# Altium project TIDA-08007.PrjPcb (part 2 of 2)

## Sheet TIDA-08007_TPS99000Interface.SchDoc: TPS99000 Interface
size 431 x 279 mm; Date: Not shown in title block; ApprovedBy: Not shown in title block; CheckedBy: Not shown in title block; Author: Not shown in title block; CompanyName: Not shown in title block; DrawnBy: Jake Pulliam; Engineer: Not shown in title block; Organization: Not shown in title block; Address1: Not shown in title block; Address2: Not shown in title block; Address3: Not shown in title block; Address4: Not shown in title block; DocumentNumber: 8; Revision: Use project parameter SCH_Rev; SheetNumber: 8; SheetTotal: 10; PageSetup: Record=PageOptions¦CenterHorizontal=True¦CenterVertical=True¦PrintScale=1.00¦XCorrection=1.00¦YCorrection=1.00¦PrintKind=0¦BorderSize=5000000¦LeftOffset=0¦BottomOffset=0¦Orientation=2¦PaperLength=1000¦PaperWidth=1000¦Scale=100¦PaperSource=15¦PrintQuality=600¦MediaType=1¦DitherType=10¦PaperKind=Letter¦PrintScaleMode=1
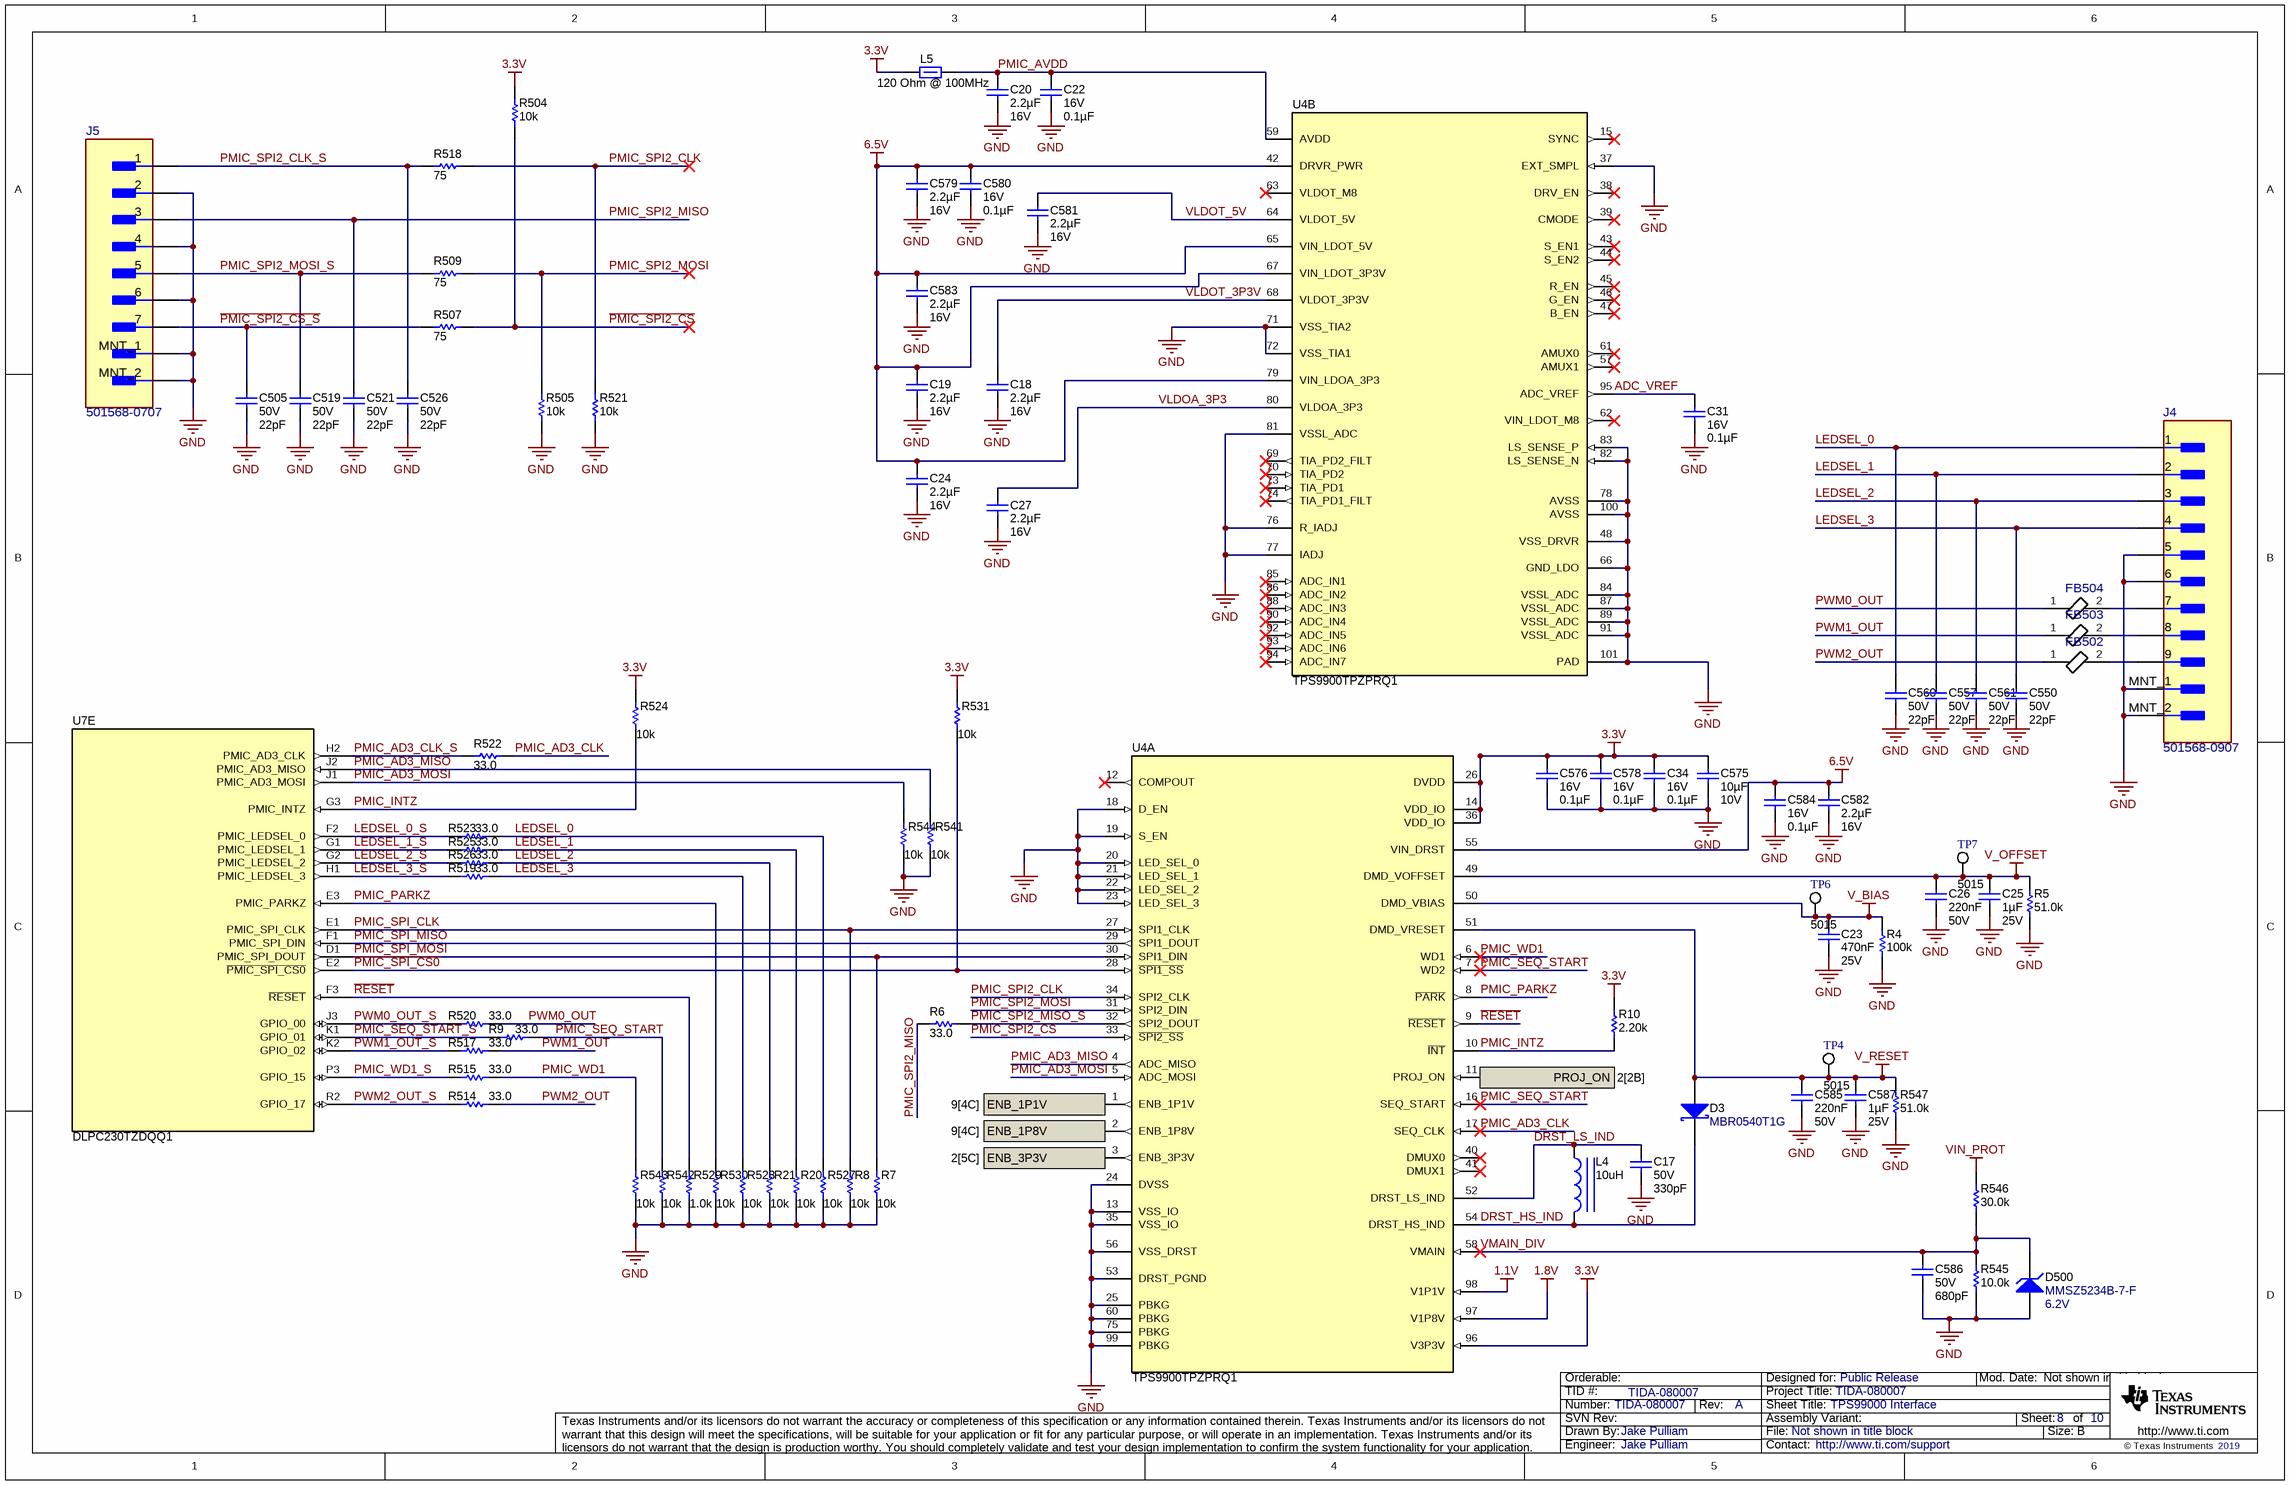
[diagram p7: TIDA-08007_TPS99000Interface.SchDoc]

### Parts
C17  VDC_V: 50V  ValueDisplayed: 330pF  [0402]  (hidden comment: GRM155R71H331KA01D)
C18  Cap_F: 2.2µF  VDC_V: 16V  [0603]  (hidden comment: EMK107BB7225MA-T)
C19  Cap_F: 2.2µF  VDC_V: 16V  [0603]  (hidden comment: EMK107BB7225MA-T)
C20  Cap_F: 2.2µF  VDC_V: 16V  [0603]  (hidden comment: EMK107BB7225MA-T)
C22  VDC_V: 16V  ValueDisplayed: 0.1µF  [0402]  (hidden comment: GCM155R71C104JA55D)
C23  Cap_F: 470nF  VDC_V: 25V  [0603]  (hidden comment: GRM188R71E474KA12D)
C24  Cap_F: 2.2µF  VDC_V: 16V  [0603]  (hidden comment: EMK107BB7225MA-T)
C25  Cap_F: 1µF  VDC_V: 25V  [0603]  (hidden comment: GCM188R71E105KA64D)
C26  Cap_F: 220nF  VDC_V: 50V  [0603]  (hidden comment: GCM188R71H224KA64D)
C27  Cap_F: 2.2µF  VDC_V: 16V  [0603]  (hidden comment: EMK107BB7225MA-T)
C31  VDC_V: 16V  ValueDisplayed: 0.1µF  [0402]  (hidden comment: GCM155R71C104JA55D)
C34  VDC_V: 16V  ValueDisplayed: 0.1µF  [0402]  (hidden comment: GCM155R71C104JA55D)
C505  VDC_V: 50V  ValueDisplayed: 22pF  [0402]  (hidden comment: CGA2B2NP01H220J050BA)
C519  VDC_V: 50V  ValueDisplayed: 22pF  [0402]  (hidden comment: CGA2B2NP01H220J050BA)
C521  VDC_V: 50V  ValueDisplayed: 22pF  [0402]  (hidden comment: CGA2B2NP01H220J050BA)
C526  VDC_V: 50V  ValueDisplayed: 22pF  [0402]  (hidden comment: CGA2B2NP01H220J050BA)
C550  VDC_V: 50V  ValueDisplayed: 22pF  [0402]  (hidden comment: CGA2B2NP01H220J050BA)
C557  VDC_V: 50V  ValueDisplayed: 22pF  [0402]  (hidden comment: CGA2B2NP01H220J050BA)
C560  VDC_V: 50V  ValueDisplayed: 22pF  [0402]  (hidden comment: CGA2B2NP01H220J050BA)
C561  VDC_V: 50V  ValueDisplayed: 22pF  [0402]  (hidden comment: CGA2B2NP01H220J050BA)
C575  Cap_F: 10µF  VDC_V: 10V  [0805_HV]  (hidden comment: C2012X7R1A106M125AC)
C576  VDC_V: 16V  ValueDisplayed: 0.1µF  [0402]  (hidden comment: GCM155R71C104JA55D)
C578  VDC_V: 16V  ValueDisplayed: 0.1µF  [0402]  (hidden comment: GCM155R71C104JA55D)
C579  Cap_F: 2.2µF  VDC_V: 16V  [0603]  (hidden comment: EMK107BB7225MA-T)
C580  VDC_V: 16V  ValueDisplayed: 0.1µF  [0402]  (hidden comment: GCM155R71C104JA55D)
C581  Cap_F: 2.2µF  VDC_V: 16V  [0603]  (hidden comment: EMK107BB7225MA-T)
C582  Cap_F: 2.2µF  VDC_V: 16V  [0603]  (hidden comment: EMK107BB7225MA-T)
C583  Cap_F: 2.2µF  VDC_V: 16V  [0603]  (hidden comment: EMK107BB7225MA-T)
C584  VDC_V: 16V  ValueDisplayed: 0.1µF  [0402]  (hidden comment: GCM155R71C104JA55D)
C585  Cap_F: 220nF  VDC_V: 50V  [0603]  (hidden comment: GCM188R71H224KA64D)
C586  VDC_V: 50V  ValueDisplayed: 680pF  [0402]  (hidden comment: CGA2B2X7R1H681K050BA)
C587  Cap_F: 1µF  VDC_V: 25V  [0603]  (hidden comment: GCM188R71E105KA64D)
D3  MBR0540T1G  [SOD-123]
D500  MMSZ5234B-7-F  value 6.2V  [SOD-123]
FB502  FBMH1608HM101-TV  [FP-FBMH1608HM101-TV_0603-MFG]  (value not drawn)
FB503  FBMH1608HM101-TV  [FP-FBMH1608HM101-TV_0603-MFG]  (value not drawn)
FB504  FBMH1608HM101-TV  [FP-FBMH1608HM101-TV_0603-MFG]  (value not drawn)
J4  501568-0907  [FP-501568-0907_HDR9-MFG]
J5  501568-0707  [FP-501568-0707_HDR7-MFG]
L4  ValueDisplayed: 10uH  [FDSD0420]  (hidden comment: FDSD0420D-100M)
L5  120 Ohm @ 100MHz  [0402]
R4  ValueDisplayed: 100k  [0402]  (hidden comment: ERJ-2RKF1003X)
R5  ValueDisplayed: 51.0k  [0402]  (hidden comment: ERJ-2RKF5102X)
R6  ValueDisplayed: 33.0  [0402]  (hidden comment: ERJ-2RKF33R0X)
R7  ValueDisplayed: 10k  [0402]  (hidden comment: ERJ-2GEJ103X)
R8  ValueDisplayed: 10k  [0402]  (hidden comment: ERJ-2GEJ103X)
R9  ValueDisplayed: 33.0  [0402]  (hidden comment: ERJ-2RKF33R0X)
R10  ValueDisplayed: 2.20k  [0402]  (hidden comment: ERJ-2RKF2201X)
R20  ValueDisplayed: 10k  [0402]  (hidden comment: ERJ-2GEJ103X)
R21  ValueDisplayed: 10k  [0402]  (hidden comment: ERJ-2GEJ103X)
R504  ValueDisplayed: 10k  [0402]  (hidden comment: ERJ-2GEJ103X)
R505  ValueDisplayed: 10k  [0402]  (hidden comment: ERJ-2GEJ103X)
R507  ValueDisplayed: 75  [0805_HV]  (hidden comment: ERJ-6GEYJ750V)
R509  ValueDisplayed: 75  [0805_HV]  (hidden comment: ERJ-6GEYJ750V)
R514  ValueDisplayed: 33.0  [0402]  (hidden comment: ERJ-2RKF33R0X)
R515  ValueDisplayed: 33.0  [0402]  (hidden comment: ERJ-2RKF33R0X)
R517  ValueDisplayed: 33.0  [0402]  (hidden comment: ERJ-2RKF33R0X)
R518  ValueDisplayed: 75  [0805_HV]  (hidden comment: ERJ-6GEYJ750V)
R519  ValueDisplayed: 33.0  [0402]  (hidden comment: ERJ-2RKF33R0X)
R520  ValueDisplayed: 33.0  [0402]  (hidden comment: ERJ-2RKF33R0X)
R521  ValueDisplayed: 10k  [0402]  (hidden comment: ERJ-2GEJ103X)
R522  ValueDisplayed: 33.0  [0402]  (hidden comment: ERJ-2RKF33R0X)
R523  ValueDisplayed: 33.0  [0402]  (hidden comment: ERJ-2RKF33R0X)
R524  ValueDisplayed: 10k  [0402]  (hidden comment: ERJ-2GEJ103X)
R525  ValueDisplayed: 33.0  [0402]  (hidden comment: ERJ-2RKF33R0X)
R526  ValueDisplayed: 33.0  [0402]  (hidden comment: ERJ-2RKF33R0X)
R527  ValueDisplayed: 10k  [0402]  (hidden comment: ERJ-2GEJ103X)
R528  ValueDisplayed: 10k  [0402]  (hidden comment: ERJ-2GEJ103X)
R529  ValueDisplayed: 1.0k  [0402]  (hidden comment: ERJ-2GEJ102X)
R530  ValueDisplayed: 10k  [0402]  (hidden comment: ERJ-2GEJ103X)
R531  ValueDisplayed: 10k  [0402]  (hidden comment: ERJ-2GEJ103X)
R541  ValueDisplayed: 10k  [0402]  (hidden comment: ERJ-2GEJ103X)
R542  ValueDisplayed: 10k  [0402]  (hidden comment: ERJ-2GEJ103X)
R543  ValueDisplayed: 10k  [0402]  (hidden comment: ERJ-2GEJ103X)
R544  ValueDisplayed: 10k  [0402]  (hidden comment: ERJ-2GEJ103X)
R545  ValueDisplayed: 10.0k  [0603]  (hidden comment: ERJ-3EKF1002V)
R546  ValueDisplayed: 30.0k  [0603]  (hidden comment: ERJ-3EKF3002V)
R547  ValueDisplayed: 51.0k  [0402]  (hidden comment: ERJ-2RKF5102X)
TP4  5015  [Testpoint_Keystone_Miniature]
TP6  5015  [Testpoint_Keystone_Miniature]
TP7  5015  [Testpoint_Keystone_Miniature]
U4  TPS9900TPZPRQ1  [PZP0100K]  (parts A,B of 2)
U7  DLPC230TZDQQ1  [ZDQ0324]  (part E of 9)

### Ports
ENB_1P1V (out, see 9[4C]), ENB_1P8V (out, see 9[4C]), ENB_3P3V (out, see 2[5C]), PROJ_ON (in, see 2[2B])

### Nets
1.1V: U4.98(V1P1V)
1.8V: U4.97(V1P8V)
3.3V: C34.1 C575.1 C576.1 C578.1 L5.1 R10.2 R504.2 R524.2 R531.2 U4.14(VDD_IO) U4.26(DVDD) U4.36(VDD_IO) U4.96(V3P3V)
6.5V: C19.1 C24.1 C579.1 C580.1 C582.1 C583.1 C584.1 U4.42(DRVR_PWR) U4.55(VIN_DRST) U4.65(VIN_LDOT_5V) U4.67(VIN_LDOT_3P3V) U4.79(VIN_LDOA_3P3)
GND: C17.2 C18.2 C19.2 C20.2 C22.2 C23.2 C24.2 C25.2 C26.2 C27.2 C31.2 C34.2 C505.2 C519.2 C521.2 C526.2 C550.2 C557.2 C560.2 C561.2 C575.2 C576.2 C578.2 C579.2 C580.2 C581.2 C582.2 C583.2 C584.2 C585.2 C586.2 C587.2 D500.2(A) J4.5 J4.6 J4.10(MNT_1) J4.11(MNT_2) J5.2 J5.4 J5.6 J5.8(MNT_1) J5.9(MNT_2) R4.1 R5.1 R7.1 R8.1 R20.1 R21.1 R505.1 R521.1 R527.1 R528.1 R529.1 R530.1 R541.1 R542.1 R543.1 R544.1 R545.1 R547.1 U4.13(VSS_IO) U4.18(D_EN) U4.19(S_EN) U4.20(LED_SEL_0) U4.21(LED_SEL_1) U4.22(LED_SEL_2) U4.23(LED_SEL_3) U4.24(DVSS) U4.25(PBKG) U4.35(VSS_IO) U4.37(EXT_SMPL) U4.48(VSS_DRVR) U4.53(DRST_PGND) U4.56(VSS_DRST) U4.60(PBKG) U4.66(GND_LDO) U4.71(VSS_TIA2) U4.72(VSS_TIA1) U4.75(PBKG) U4.76(R_IADJ) U4.77(IADJ) U4.78(AVSS) U4.81(VSSL_ADC) U4.82(LS_SENSE_N) U4.83(LS_SENSE_P) U4.84(VSSL_ADC) U4.87(VSSL_ADC) U4.89(VSSL_ADC) U4.91(VSSL_ADC) U4.99(PBKG) U4.100(AVSS) U4.101(PAD)
V_BIAS: C23.1 R4.2 TP6.1 U4.50(DMD_VBIAS)
V_OFFSET: C25.1 C26.1 R5.2 TP7.1 U4.49(DMD_VOFFSET)
V_RESET: C585.1 C587.1 D3.2(A) R547.2 TP4.1 U4.51(DMD_VRESET)
VIN_PROT: R546.2
~{PMIC_SPI2_CS}: R504.1 R507.2 U4.33(~{SPI2_SS})
~{PMIC_SPI2_CS_S}: C505.1 J5.7 R507.1
~{PMIC_SPI_CS0}: R531.1 U4.28(~{SPI1_SS}) U7.E2(~{PMIC_SPI_CS0})
~{RESET}: R529.2 U4.9(~{RESET}) U7.F3(~{RESET})
ADC_VREF: C31.1 U4.95(ADC_VREF)
DRST_HS_IND: D3.1(K) L4.2 U4.54(DRST_HS_IND)
DRST_LS_IND: C17.1 L4.1 U4.52(DRST_LS_IND)
ENB_1P1V: U4.1(ENB_1P1V) ; port ENB_1P1V
ENB_1P8V: U4.2(ENB_1P8V) ; port ENB_1P8V
ENB_3P3V: U4.3(ENB_3P3V) ; port ENB_3P3V
LEDSEL_0: C560.1 J4.1 R523.2 R527.2
LEDSEL_0_S: R523.1 U7.F2(PMIC_LEDSEL_0)
LEDSEL_1: C557.1 J4.2 R20.2 R525.2
LEDSEL_1_S: R525.1 U7.G1(PMIC_LEDSEL_1)
LEDSEL_2: C561.1 J4.3 R21.2 R526.2
LEDSEL_2_S: R526.1 U7.G2(PMIC_LEDSEL_2)
LEDSEL_3: C550.1 J4.4 R519.2 R528.2
LEDSEL_3_S: R519.1 U7.H1(PMIC_LEDSEL_3)
PMIC_AD3_CLK: R522.2 U4.17(SEQ_CLK)
PMIC_AD3_CLK_S: R522.1 U7.H2(PMIC_AD3_CLK)
PMIC_AD3_MISO: R541.2 U4.4(ADC_MISO) U7.J2(PMIC_AD3_MISO)
PMIC_AD3_MOSI: R544.2 U4.5(ADC_MOSI) U7.J1(PMIC_AD3_MOSI)
PMIC_AVDD: C20.1 C22.1 L5.2 U4.59(AVDD)
PMIC_INTZ: R10.1 R524.1 U4.10(~{INT}) U7.G3(PMIC_INTZ)
PMIC_PARKZ: R530.2 U4.8(~{PARK}) U7.E3(PMIC_PARKZ)
PMIC_SEQ_START: R9.2 R542.2 U4.7(WD2) U4.16(SEQ_START)
PMIC_SEQ_START_S: R9.1 U7.K1(GPIO_01)
PMIC_SPI2_CLK: R518.2 R521.2 U4.34(SPI2_CLK)
PMIC_SPI2_CLK_S: C526.1 J5.1 R518.1
PMIC_SPI2_MISO: C521.1 J5.3 R6.1
PMIC_SPI2_MISO_S: R6.2 U4.32(SPI2_DOUT)
PMIC_SPI2_MOSI: R505.2 R509.2 U4.31(SPI2_DIN)
PMIC_SPI2_MOSI_S: C519.1 J5.5 R509.1
PMIC_SPI_CLK: R8.2 U4.27(SPI1_CLK) U7.E1(PMIC_SPI_CLK)
PMIC_SPI_MISO: U4.29(SPI1_DOUT) U7.F1(PMIC_SPI_DIN)
PMIC_SPI_MOSI: R7.2 U4.30(SPI1_DIN) U7.D1(PMIC_SPI_DOUT)
PMIC_WD1: R515.2 R543.2 U4.6(WD1)
PMIC_WD1_S: R515.1 U7.P3(GPIO_15)
PROJ_ON: U4.11(PROJ_ON) ; port PROJ_ON
PWM0_OUT: FB504.1 R520.2
PWM0_OUT_S: R520.1 U7.J3(GPIO_00)
PWM1_OUT: FB503.1 R517.2
PWM1_OUT_S: R517.1 U7.K2(GPIO_02)
PWM2_OUT: FB502.1 R514.2
PWM2_OUT_S: R514.1 U7.R2(GPIO_17)
VLDOA_3P3: C27.1 U4.80(VLDOA_3P3)
VLDOT_3P3V: C18.1 U4.68(VLDOT_3P3V)
VLDOT_5V: C581.1 U4.64(VLDOT_5V)
VMAIN_DIV: C586.1 D500.1(K) R545.2 R546.1 U4.58(VMAIN)
NetFB502_2: FB502.2 J4.9
NetFB503_2: FB503.2 J4.8
NetFB504_2: FB504.2 J4.7

Not connected (* = marked no-connect by the designer): U4 12(COMPOUT)* 15(SYNC)* 38(DRV_EN)* 39(CMODE)* 40(DMUX0)* 41(DMUX1)* 43(S_EN1)* 44(S_EN2)* 45(R_EN)* 46(G_EN)* 47(B_EN)* 57(AMUX1)* 61(AMUX0)* 62(VIN_LDOT_M8)* 63(VLDOT_M8)* 69(TIA_PD2_FILT)* 70(TIA_PD2)* 73(TIA_PD1)* 74(TIA_PD1_FILT)* 85(ADC_IN1)* 86(ADC_IN2)* 88(ADC_IN3)* 90(ADC_IN4)* 92(ADC_IN5)* 93(ADC_IN6)* 94(ADC_IN7)*

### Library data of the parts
C17 = CMP-0006687-2: CAP, CERM, 330 pF, 50 V, +/- 10%, X7R, 0402; Manufacturer: MuRata; TaMin_C: -55°C; Polarized: N; SizeAreaWB_mm2: 3; Value1: Unknown; U/M: EA; Value: 330pF; TaMax_C: 125°C; SizeZ_mm: 0.6; SizeX_mm: 1; SizeY_mm: 0.5; AEC Category: Q200
C18-C20 C24 C27 C579 C581-C583 = CMP-0064934-4: CAP, CERM, 2.2 uF, 16 V,+/- 10%, X7R, 0603; Manufacturer: Taiyo Yuden; TaMin_C: -55°C; Polarized: N; SizeAreaWB_mm2: 4.68; Value1: Unknown; U/M: EA; Value: 2.2uF; TaMax_C: 125°C; SizeZ_mm: 1; SizeX_mm: 1.6; SizeY_mm: 0.8; SizeArea_mm2: 1.28; AEC Category: Q200
C22 C31 C34 C576 C578 C580 C584 = CMP-0080702-1: CAP, CERM, 0.1 µF, 16 V,+/- 5%, X7R, AEC-Q200 Grade 1, 0402; Manufacturer: MuRata; Cap_F: 100nF; SizeAreaWB_mm2: 3; SizeArea_mm2: 0.5; AEC Qualified: Y; AEC Category: Q200; Value: 0.1uF; TaMax_C: 125°C; SizeZ_mm: 0.6; AEC Grade: 1; Polarized: N; TaMin_C: -55°C; U/M: EA
C23 = CMP-0007424-4: CAP, CERM, 0.47 uF, 25 V, +/- 10%, X7R, 0603; Manufacturer: MuRata; TaMin_C: -55°C; Polarized: N; SizeAreaWB_mm2: 4.68; Value1: Unknown; U/M: EA; Value: 0.47uF; TaMax_C: 125°C; SizeZ_mm: 1; SizeX_mm: 1.6; SizeY_mm: 0.8; SizeArea_mm2: 1.28; AEC Category: Q200
C25 C587 = CMP-0007139-4: CAP, CERM, 1 uF, 25 V, +/- 10%, X7R, AEC-Q200 Grade 1, 0603; Manufacturer: MuRata; TaMin_C: -55°C; Polarized: N; SizeAreaWB_mm2: 4.68; Value1: Unknown; U/M: EA; Value: 1uF; TaMax_C: 125°C; SizeZ_mm: 1; SizeX_mm: 1.6; SizeY_mm: 0.8; SizeArea_mm2: 1.28; AEC Qualified: Y; AEC Category: Q200
C26 C585 = CMP-0007145-4: CAP, CERM, 0.22 uF, 50 V, +/- 10%, X7R, AEC-Q200 Grade 1, 0603; Manufacturer: MuRata; TaMin_C: -55°C; Polarized: N; SizeAreaWB_mm2: 4.68; Value1: Unknown; U/M: EA; Value: 0.22uF; TaMax_C: 125°C; SizeZ_mm: 1; SizeX_mm: 1.6; SizeY_mm: 0.8; SizeArea_mm2: 1.28; AEC Qualified: Y; AEC Category: Q200
C505 C519 C521 C526 C550 C557 C560 C561 = CMP-0006311-2: CAP, CERM, 22 pF, 50 V, +/- 5%, C0G/NP0, AEC-Q200 Grade 1, 0402; Manufacturer: TDK; TaMin_C: -55°C; Polarized: N; SizeAreaWB_mm2: 3; Value1: Unknown; U/M: EA; Value: 22pF; TaMax_C: 125°C; SizeZ_mm: 0.6; SizeX_mm: 1; SizeY_mm: 0.5; AEC Qualified: Y; AEC Category: Q200
C575 = CMP-0007864-2: CAP, CERM, 10 uF, 10 V, +/- 20%, X7R, 0805; Manufacturer: TDK; TaMin_C: -55°C; Polarized: N; SizeAreaWB_mm2: 6.75; Value1: Unknown; U/M: EA; Value: 10uF; TaMax_C: 125°C; SizeZ_mm: 1.45; SizeX_mm: 2; SizeY_mm: 1.25; Cap_Case: 0805; SizeArea_mm2: 2.5; AEC Category: Q200
C586 = CMP-0006322-2: CAP, CERM, 680 pF, 50 V, +/- 10%, X7R, AEC-Q200 Grade 1, 0402; Manufacturer: TDK; TaMin_C: -55°C; ESR_ohm: 3.07785; Polarized: N; SizeAreaWB_mm2: 3; Value1: 3.07785 ohm; U/M: EA; Value: 680pF; TaMax_C: 125°C; SizeZ_mm: 0.6; SizeX_mm: 1; SizeY_mm: 0.5; AEC Qualified: Y; IRMS_A: 257.63mA; AEC Category: Q200
D3 = CMP-0028526-2: Diode, Schottky, 40 V, 0.5 A, SOD-123; Manufacturer: ON Semiconductor; Green_REACh: Passed; SizeY_mm: 1.7; Io_A: 500mA; SizeArea_mm2: 6.545; RJC_CperW: 118; Green_Lifecycle: Active; Vr_V: 40V; Vf_V: 510mV; TJmax_C: 150°C; AEC Category: Q101; SizeAreaWB_mm2: 13.095; Value1: 0.5A; SizeZ_mm: 1.35; SizeX_mm: 3.85; Value2: 0.51V; Value: 40V
D500 = CMP-0005805-3: Diode, Zener, 6.2 V, 500 mW, SOD-123; Manufacturer: Diodes Inc.; SizeY_mm: 1.7; AEC Category: Q101; SizeAreaWB_mm2: 13.095; SizeZ_mm: 1.35; SizeArea_mm2: 6.545; RJA_CperW: 350; Power_W: 500mW; Value1: 0.5W; SizeX_mm: 3.85
FB502-FB504 = CMP-0086561-1: Ind Chip Bead Multi-Layer 100Ohm 25% 100MHz Ferrite 2.5A 0603 T/R; Manufacturer: Taiyo Yuden; Symbol Name: SYM-FBMH1608HM101-TV; SizeZ_mm: 0.9mm; DCR_ohm: 0.035
J4 = CMP-0086592-1: CONN HEADER SMD R/A 9POS 1MM; Manufacturer: Molex; Row_Count: 1; Current_A: 1A; Symbol Name: SYM-501568-0907; ContactFinish: Tin,Nickel; Voltage_V: 50V
J5 = CMP-0087313-1: CONN HEADER 1MM 7POS SMD R/A; Manufacturer: Molex; Voltage_V: 50V; Row_Count: 1; ContactFinish: Tin,Nickel; Current_A: 1A
L4 = CMP-0058981-1: Inductor, Shielded, 10 uH, 1.7 A, 0.2 ohm, AEC-Q200 Grade 1, SMD; Manufacturer: MuRata Toko; Isat: 1.7A @ 30% inductance drop; Irms: 2.5A @ 40C rise; SizeAreaWB_mm2: 27.04; DCR_ohm: 0.2; Value1: 0.2 ohm; Value: 10uH; Imax_A: 1.7A; SizeZ_mm: 2; SizeX_mm: 4.2; SizeArea_mm2: 17.64; Ind_H: 10µH; AEC Qualified: Y; AEC Grade: 1; AEC Category: Q200
L5 = CMP-0075677-1: Ferrite Bead, 120 ohm @ 100 MHz, 0.4 A, 0402; Manufacturer: TDK; PartNumber: MMZ1005Y121CT000; ZTyp@100MHz_Ohm: 120; SizeAreaWB_mm2: 3.0; DCR_ohm: 0.18; Value1: 0.18 ohm; Value: 120 ohm; Imax_A: 400mA; SizeZ_mm: 0.6; SizeX_mm: 1.0; SizeY_mm: 0.5; Value2: 0.4A
R4 = CMP-0026659-1: RES, 100 k, 1%, 0.1 W, 0402; Manufacturer: Panasonic; Power_W: 100mW; TempCo: 100 ppm/C; U/M: EA; Value: 100k; EIA_Code: E96; SizeX_mm: 1; SizeY_mm: 0.5; SizeZ_mm: 0.6; Value2: 0.1W; VDC_V: 50V; AEC Category: Q200
R5 R547 = CMP-0026705-1: RES, 51.0 k, 1%, 0.1 W, AEC-Q200 Grade 0, 0402; Manufacturer: Panasonic; Power_W: 100mW; TempCo: 100 ppm/C; Value_Code: 51k0; U/M: EA; Value: 51.0k; Res_ohm: 51k; SizeX_mm: 1; SizeY_mm: 0.5; SizeZ_mm: 0.6; Value2: 0.1W; AEC Qualified: Y; VDC_V: 50V; AEC Grade: 0; AEC Category: Q200
R6 R9 R514 R515 R517 R519 R520 R522 R523 R525 R526 = CMP-0026696-1: RES, 33.0, 1%, 0.1 W, 0402; Manufacturer: Panasonic; Power_W: 100mW; TempCo: 100 ppm/C; Value_Code: 33R0; U/M: EA; Value: 33.0; Res_ohm: 33; SizeX_mm: 1; SizeY_mm: 0.5; SizeZ_mm: 0.6; Value2: 0.1W; VDC_V: 50V; AEC Category: Q200
R7 R8 R20 R21 R504 R505 R521 R524 R527 R528 R530 R531 R541-R544 = CMP-0026994-4: RES, 10 k, 5%, 0.1 W, AEC-Q200 Grade 0, 0402; Manufacturer: Panasonic; Power_W: 100mW; TempCo: 200 ppm/C; Value_Code: 10k0; U/M: EA; Value: 10k; EIA_Code: E24; SizeX_mm: 1; SizeY_mm: 0.5; SizeZ_mm: 0.6; Value2: 0.1W; AEC Qualified: Y; VDC_V: 50V; AEC Grade: 0; AEC Category: Q200
R10 = CMP-0026681-1: RES, 2.20 k, 1%, 0.1 W, 0402; Manufacturer: Panasonic; Power_W: 100mW; TempCo: 100 ppm/C; Value_Code: 2k20; U/M: EA; Value: 2.20k; Res_ohm: 2.2k; SizeX_mm: 1; SizeY_mm: 0.5; SizeZ_mm: 0.6; Value2: 0.1W; VDC_V: 50V; AEC Category: Q200
R507 R509 R518 = CMP-0020766-3: RES, 75, 5%, 0.125 W, AEC-Q200 Grade 0, 0805; Manufacturer: Panasonic; Power_W: 125mW; TempCo: 200 ppm/C; Value_Code: 75R0; Value: 75; EIA_Code: E24; SizeX_mm: 2; SizeY_mm: 1.25; SizeZ_mm: 1.45; Value2: 0.125W; SizeArea_mm2: 2.5; AEC Qualified: Y; VDC_V: 150V; AEC Category: Q200; AEC Grade: 0; SizeAreaWB_mm2: 6.75
R529 = CMP-0078193-1: RES, 1.0 k, 5%, 0.1 W, AEC-Q200 Grade 0, 0402; Manufacturer: Panasonic; Value_Code: 1k00; SizeArea_mm2: 0.5; AEC Qualified: Y; AEC Category: Q200; Res_ohm: 1k; Value: 1.0k; SizeZ_mm: 0.6; Green_REACh: Passed; EIA_Code: E24; TempCo: 200 ppm/C; AEC Grade: 0; Power_W: 100mW; VDC_V: 50V; Value2: 0.1W; Green_Lifecycle: Active; U/M: EA; SizeX_mm: 1
R545 = CMP-0022684-3: RES, 10.0 k, 1%, 0.1 W, 0603; Manufacturer: Panasonic; Power_W: 100mW; TempCo: 100 ppm/C; Value_Code: 10k0; U/M: EA; Value: 10.0k; EIA_Code: E96; Res_ohm: 10k; SizeX_mm: 1.6; SizeY_mm: 0.8; SizeZ_mm: 1; Value2: 0.1W; SizeArea_mm2: 1.28; VDC_V: 75V; AEC Category: Q200
R546 = CMP-0022695-3: RES, 30.0 k, 1%, 0.1 W, AEC-Q200 Grade 0, 0603; Manufacturer: Panasonic; Power_W: 100mW; TempCo: 100 ppm/C; Value_Code: 30k0; U/M: EA; Value: 30.0k; Res_ohm: 30k; SizeX_mm: 1.6; SizeY_mm: 0.8; SizeZ_mm: 1; Value2: 0.1W; SizeArea_mm2: 1.28; AEC Qualified: Y; VDC_V: 75V; AEC Grade: 0; AEC Category: Q200
TP4 TP6 TP7 = CMP-0055152-1: Test Point, Miniature, SMT; Manufacturer: Keystone; CNHeader: FALSE; Green_Lifecycle: Active; Green_REACh: Passed; CT: TRUE
U4 = CMP-0750180-3: DLP® System Management and Illumination Controller for DLP553x-Q1 Chipset, PZP0100K (TQFP-100); Alternate Manufacturer: Texas Instruments; SizeX_mm: 16; Rating: Automotive; AEC Qualified: Y; SizeZ_mm: 1.2; SizeAreaWB_mm2: 324; AEC Category: Q200; CompType: IC; SizeArea_mm2: 256
U7 = CMP-0750177-3: DLP® Automotive DMD Controller for DLP553x-Q1 Chipset, ZDQ0324 (BGA-324); Manufacturer: Texas Instruments; SizeAreaWB_mm2: 625; SizeArea_mm2: 529; SizeX_mm: 23; AEC Qualified: Y; CompType: IC; AEC Category: Q200; SizeZ_mm: 2.352

## Sheet TIDA-08007_Power.SchDoc: Power
size 431 x 279 mm; Date: Not shown in title block; ApprovedBy: Not shown in title block; CheckedBy: Not shown in title block; Author: Not shown in title block; CompanyName: Not shown in title block; DrawnBy: Jake Pulliam; Engineer: Not shown in title block; Organization: Not shown in title block; Address1: Not shown in title block; Address2: Not shown in title block; Address3: Not shown in title block; Address4: Not shown in title block; DocumentNumber: 9; Revision: Use project parameter SCH_Rev; SheetNumber: 9; SheetTotal: 10; PageSetup: Record=PageOptions¦CenterHorizontal=True¦CenterVertical=True¦PrintScale=1.00¦XCorrection=1.00¦YCorrection=1.00¦PrintKind=0¦BorderSize=5000000¦LeftOffset=0¦BottomOffset=0¦Orientation=2¦PaperLength=1000¦PaperWidth=1000¦Scale=100¦PaperSource=15¦PrintQuality=600¦MediaType=1¦DitherType=10¦PaperKind=Letter¦PrintScaleMode=1
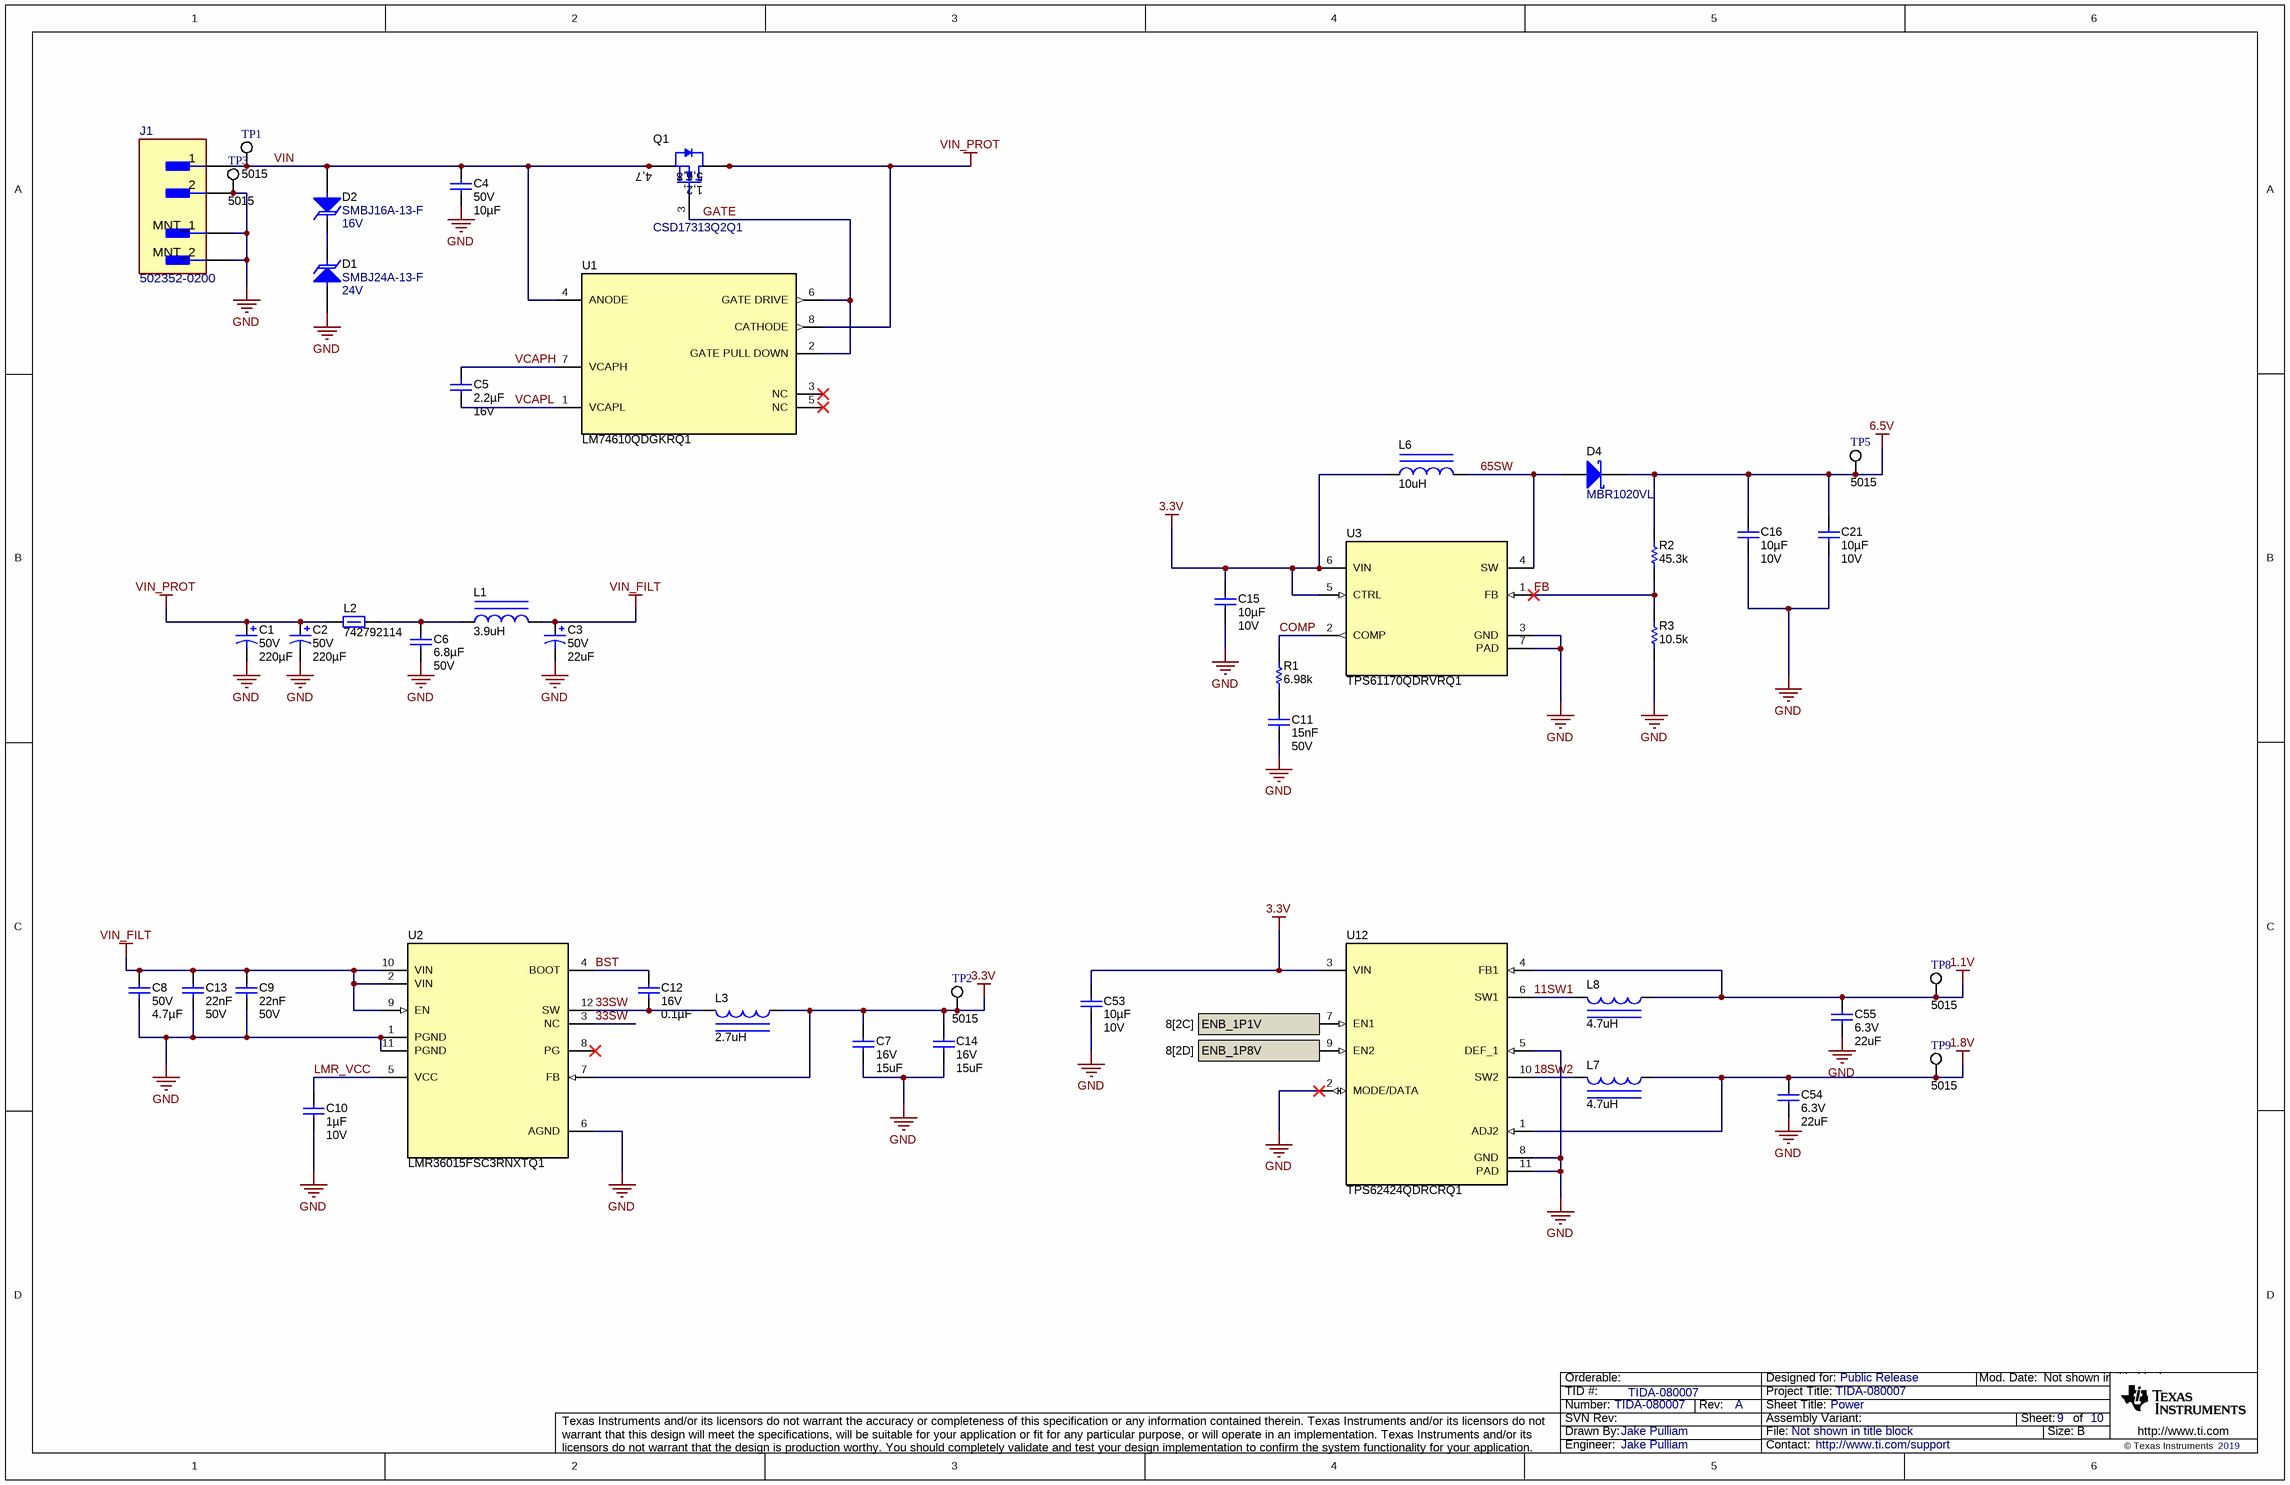
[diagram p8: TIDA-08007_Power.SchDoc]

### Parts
C1  VDC_V: 50V  ValueDisplayed: 220µF  [CAPSMT_62_HA0]  (hidden comment: EMZR500ARA221MHA0G)
C2  VDC_V: 50V  ValueDisplayed: 220µF  [CAPSMT_62_HA0]  (hidden comment: EMZR500ARA221MHA0G)
C3  VDC_V: 50V  ValueDisplayed: 22uF  [CAPSMT_62_F55]  (hidden comment: EMVA500ADA220MF55G)
C4  VDC_V: 50V  ValueDisplayed: 10µF  [1210_270]  (hidden comment: CL32B106KBJNNWE)
C5  Cap_F: 2.2µF  VDC_V: 16V  [0603]  (hidden comment: EMK107BB7225MA-T)
C6  ValueDisplayed: 6.8µF  VDC_V: 50V  [1812_280]  (hidden comment: C4532X7R1H685M250KB)
C7  VDC_V: 16V  ValueDisplayed: 15uF  [0805_HV]  (hidden comment: C2012X6S1C156M125AC)
C8  VDC_V: 50V  ValueDisplayed: 4.7µF  [1206_180]  (hidden comment: GCM31CC71H475KA03L)
C9  Cap_F: 22nF  VDC_V: 50V  [0603]  (hidden comment: C0603C223K5RACTU)
C10  Cap_F: 1µF  VDC_V: 10V  [0805_HV]  (hidden comment: LMK212B7105KG-T)
C11  Cap_F: 15nF  VDC_V: 50V  [0805_HV]  (hidden comment: 08055C153KAT2A)
C12  VDC_V: 16V  ValueDisplayed: 0.1µF  [0402]  (hidden comment: GCM155R71C104JA55D)
C13  Cap_F: 22nF  VDC_V: 50V  [0603]  (hidden comment: C0603C223K5RACTU)
C14  VDC_V: 16V  ValueDisplayed: 15uF  [0805_HV]  (hidden comment: C2012X6S1C156M125AC)
C15  Cap_F: 10µF  VDC_V: 10V  [0805_HV]  (hidden comment: C2012X7R1A106M125AC)
C16  Cap_F: 10µF  VDC_V: 10V  [0805_HV]  (hidden comment: C2012X7R1A106M125AC)
C21  Cap_F: 10µF  VDC_V: 10V  [0805_HV]  (hidden comment: C2012X7R1A106M125AC)
C53  Cap_F: 10µF  VDC_V: 10V  [0805_HV]  (hidden comment: C2012X7R1A106M125AC)
C54  VDC_V: 6.3V  ValueDisplayed: 22uF  [1206_180]  (hidden comment: CGA5L1X7R0J226M160AC)
C55  VDC_V: 6.3V  ValueDisplayed: 22uF  [1206_180]  (hidden comment: CGA5L1X7R0J226M160AC)
D1  SMBJ24A-13-F  value 24V  [SMB]
D2  SMBJ16A-13-F  value 16V  [SMB]
D4  MBR1020VL  [SOD-123F]
J1  502352-0200  [FP-502352-0200_HDR2-MFG]
L1  ValueDisplayed: 3.9uH  [WE-PD2-S]  (hidden comment: 744773039)
L2  742792114  [1206]
L3  ValueDisplayed: 2.7uH  [SDE0604A]  (hidden comment: SDE0604A-2R7M)
L6  ValueDisplayed: 10uH  [VLCF5020]  (hidden comment: VLCF5020T-100M1R1-1)
L7  ValueDisplayed: 4.7uH  [WE-MAIA_3015]  (hidden comment: 78438335047)
L8  ValueDisplayed: 4.7uH  [WE-MAIA_3015]  (hidden comment: 78438335047)
Q1  CSD17313Q2Q1  [DQK0006C]
R1  ValueDisplayed: 6.98k  [0402]  (hidden comment: CRCW04026K98FKED)
R2  ValueDisplayed: 45.3k  [0402]  (hidden comment: CRCW040245K3FKED)
R3  ValueDisplayed: 10.5k  [0805_HV]  (hidden comment: CRCW080510K5FKEA)
TP1  5015  [Testpoint_Keystone_Miniature]
TP2  5015  [Testpoint_Keystone_Miniature]
TP3  5015  [Testpoint_Keystone_Miniature]
TP5  5015  [Testpoint_Keystone_Miniature]
TP8  5015  [Testpoint_Keystone_Miniature]
TP9  5015  [Testpoint_Keystone_Miniature]
U1  LM74610QDGKRQ1  [DGK0008A_N]
U2  LMR36015FSC3RNXTQ1  [RNX0012B]
U3  TPS61170QDRVRQ1  [DRV0006A]
U12  TPS62424QDRCRQ1  [DRC0010J]

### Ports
ENB_1P1V (in, see 8[2C]), ENB_1P8V (in, see 8[2D])

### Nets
1.1V: C55.1 L8.1 TP8.1 U12.4(FB1)
1.8V: C54.1 L7.1 TP9.1 U12.1(ADJ2)
3.3V: C7.1 C14.1 C15.1 C53.1 L3.2 L6.1 TP2.1 U2.7(FB) U3.5(CTRL) U3.6(VIN) U12.3(VIN)
6.5V: C16.1 C21.1 D4.1(K) R2.2 TP5.1
GND: C1.2(-) C2.2(-) C3.2(-) C4.2 C6.2 C7.2 C8.1 C9.2 C10.2 C11.2 C13.2 C14.2 C15.2 C16.2 C21.2 C53.2 C54.2 C55.2 D1.2(A) J1.2 J1.3(MNT_1) J1.4(MNT_2) R3.1 TP3.1 U2.1(PGND) U2.6(AGND) U2.11(PGND) U3.3(GND) U3.7(PAD) U12.2(MODE/DATA) U12.5(DEF_1) U12.8(GND) U12.11(PAD)
VIN_FILT: C3.1(+) C8.2 C9.1 C13.1 L1.2 U2.2(VIN) U2.9(EN) U2.10(VIN)
VIN_PROT: C1.1(+) C2.1(+) L2.1 Q1.1(D) Q1.2(D) Q1.5(D) Q1.6(D) Q1.8(D) U1.8(CATHODE)
11SW1: L8.2 U12.6(SW1)
18SW2: L7.2 U12.10(SW2)
33SW: C12.2 L3.1 U2.3(NC) U2.12(SW)
65SW: D4.2(A) L6.2 U3.4(SW)
BST: C12.1 U2.4(BOOT)
COMP: R1.2 U3.2(COMP)
ENB_1P1V: U12.7(EN1) ; port ENB_1P1V
ENB_1P8V: U12.9(EN2) ; port ENB_1P8V
FB: R2.1 R3.2 U3.1(FB)
GATE: Q1.3(G) U1.2(GATE_PULL_DOWN) U1.6(GATE_DRIVE)
LMR_VCC: C10.1 U2.5(VCC)
VCAPH: C5.1 U1.7(VCAPH)
VCAPL: C5.2 U1.1(VCAPL)
VIN: C4.1 D2.2(A) J1.1 Q1.4(S) Q1.7(S) TP1.1 U1.4(ANODE)
NetC6_1: C6.1 L1.1 L2.2
NetC11_1: C11.1 R1.1
NetD1_1: D1.1(K) D2.1(K)

Not connected (* = marked no-connect by the designer): U1 3(NC)* 5(NC)*; U2 8(PG)*

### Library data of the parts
C1 C2 = CMP-0086092-1: CAP, AL, 220 µF, 50 V, +/- 20%, AEC-Q200 Grade 2, SMD; Manufacturer: Chemi-Con; TaMin_C: -55°C; U/M: EA; SizeX_mm: 8.3; Value: 220uF; Cap_Case: HA0; SizeArea_mm2: 68.89; CompType: Capacitor; SizeAreaWB_mm2: 106.09; SizeZ_mm: 10; AEC Category: Q200; AEC Grade: 2; AEC Qualified: Y; TaMax_C: 105°C
C3 = CMP-0011237-3: CAP, AL, 22 uF, 50 V, +/- 20%, SMD; Manufacturer: Chemi-Con; TaMin_C: -40°C; Polarized: Y; SizeAreaWB_mm2: 77.44; Value1: Unknown; U/M: EA; Value: 22uF; TaMax_C: 85°C; SizeZ_mm: 5.5; SizeX_mm: 6.8; Cap_Case: F55; SizeArea_mm2: 46.24; CompType: Capacitor; Cap_F: 22µF; IRMS_A: 47mA; AEC Category: Q200
C4 = CMP-0079201-1: CAP, CERM, 10 µF, 50 V,+/- 10%, X7R, 1210; Manufacturer: Samsung Electro-Mechanics; TaMin_C: -55°C; ESR_ohm: 5m; Polarized: N; SizeAreaWB_mm2: 14.7; Value1: 0.005 ohm; U/M: EA; Value: 10uF; TaMax_C: 125°C; SizeZ_mm: 2.7; SizeX_mm: 3.2; SizeY_mm: 2.5; Cap_Case: 1210; SizeArea_mm2: 8; AEC Category: Q200
C5 = CMP-0064934-4: as C18-C20 on sheet TIDA-08007_TPS99000Interface
C6 = CMP-0860184-1: CAP, CERM, 6.8 µF, 50 V,+/- 20%, X7R, 1812; Manufacturer: TDK; Cap_Case: 1812; SizeZ_mm: 2.8; Polarized: N; Green_Lifecycle: Active; Green_REACh: Passed; SizeY_mm: 3.2; TaMax_C: 125°C; Value: 6.8uF; AEC Category: Q200; TaMin_C: -55°C; SizeX_mm: 4.5; SizeArea_mm2: 14.4; SizeAreaWB_mm2: 23.1; U/M: EA
C7 C14 = CMP-0007851-1: CAP, CERM, 15 uF, 16 V, +/- 20%, X6S, 0805; Manufacturer: TDK; TaMin_C: -55°C; ESR_ohm: 1.669m; Polarized: N; SizeAreaWB_mm2: 6.75; Value1: 0.001669 ohm; U/M: EA; Value: 15uF; TaMax_C: 105°C; SizeZ_mm: 1.45; SizeX_mm: 2; SizeY_mm: 1.25; Cap_Case: 0805; SizeArea_mm2: 2.5; Cap_F: 15µF; IRMS_A: 5.04984A; AEC Category: Q200
C8 = CMP-0085643-1: CAP, CERM, 4.7 µF, 50 V,+/- 10%, X7S, AEC-Q200 Grade 1, 1206; Manufacturer: MuRata; SizeZ_mm: 1.8; Polarized: N; AEC Category: Q200; SizeY_mm: 1.6; SizeAreaWB_mm2: 10.92; SizeArea_mm2: 5.12; Value: 4.7uF; TaMin_C: -55°C; AEC Qualified: Y; SizeX_mm: 3.2; AEC Grade: 1; Cap_Case: 1206; U/M: EA; TaMax_C: 125°C
C9 C13 = CMP-0006901-4: CAP, CERM, 0.022 uF, 50 V, +/- 10%, X7R, 0603; Manufacturer: Kemet; TaMin_C: -55°C; Polarized: N; Value1: Unknown; U/M: EA; TaMax_C: 125°C; SizeAreaWB_mm2: 4.68; SizeZ_mm: 1; SizeX_mm: 1.6; SizeY_mm: 0.8; SizeArea_mm2: 1.28; AEC Category: Q200
C10 = CMP-0008397-2: CAP, CERM, 1 uF, 10 V, +/- 10%, X7R, 0805; Manufacturer: Taiyo Yuden; TaMin_C: -55°C; Polarized: N; SizeAreaWB_mm2: 6.75; Value1: Unknown; U/M: EA; Value: 1uF; TaMax_C: 125°C; SizeZ_mm: 1.45; SizeX_mm: 2; SizeY_mm: 1.25; Cap_Case: 0805; SizeArea_mm2: 2.5; AEC Category: Q200
C11 = CMP-0007639-2: CAP, CERM, 0.015 uF, 50 V, +/- 10%, X7R, 0805; Manufacturer: AVX; TaMin_C: -55°C; ESR_ohm: 0.063; Polarized: N; SizeAreaWB_mm2: 6.75; Value1: 0.063 ohm; U/M: EA; TaMax_C: 125°C; SizeZ_mm: 1.45; SizeX_mm: 2; SizeY_mm: 1.25; Cap_Case: 0805; SizeArea_mm2: 2.5; AEC Category: Q200
C12 = CMP-0080702-1: as C22 on sheet TIDA-08007_TPS99000Interface
C15 C16 C21 C53 = CMP-0007864-2: as C575 on sheet TIDA-08007_TPS99000Interface
C54 C55 = CMP-0008770-2: CAP, CERM, 22 uF, 6.3 V, +/- 10%, X7R, AEC-Q200 Grade 1, 1206; Manufacturer: TDK; TaMin_C: -55°C; ESR_ohm: 1.872m; Polarized: N; SizeAreaWB_mm2: 10.92; Value1: 0.001872 ohm; U/M: EA; Value: 22uF; SizeZ_mm: 1.8; SizeX_mm: 3.2; SizeY_mm: 1.6; SizeArea_mm2: 5.12; AEC Qualified: Y; Cap_F: 22µF; IRMS_A: 5.30203A; AEC Grade: 1; AEC Category: Q200; TaMax_C: 125°C
D1 = CMP-0005557-4: Diode, TVS, Uni, 24 V, 38.9 Vc, SMB; Manufacturer: Diodes Inc.; Value1: 600W; SizeArea_mm2: 21.336; Vbr_Max: 30.7V; SizeY_mm: 3.81; Vbr_Min: 26.7V; SizeX_mm: 5.6; SizeAreaWB_mm2: 44.156; Vc: 38.9V; SizeZ_mm: 2.6; Ipp: 15.4A; AEC Category: Q101
D2 = CMP-0005547-4: Diode, TVS, Uni, 16 V, 26 Vc, SMB; Manufacturer: Diodes Inc.; SizeArea_mm2: 21.336; SizeY_mm: 3.81; Vbr_Min: 17.8V; Ppk: 600W; AEC Category: Q101; SizeZ_mm: 2.6; Ipp: 23.1A; SizeAreaWB_mm2: 44.156; Vc: 26V; Vbr_Max: 20.5V; SizeX_mm: 5.6
D4 = CMP-0028797-2: Diode, Schottky, 20 V, 1 A, SOD-123F; Manufacturer: Fairchild Semiconductor; SizeX_mm: 3.5; AEC Qualified: N; Value: 20V; TJmax_C: 125°C; Green_REACh: Incomplete; Value2: 0.34V; SizeZ_mm: 1.1; Green_Lifecycle: Not Set; AEC Category: Q101; Value1: 1A; SizeAreaWB_mm2: 11.7; Vf_V: 340mV; SizeY_mm: 1.6; SizeArea_mm2: 5.6
J1 = CMP-0087312-1: CONN HEADER SMD R/A 2POS 2MM; Manufacturer: Molex; ContactFinish: Tin,Nickel; Current_A: 3A; Voltage_V: 125V; Row_Count: 1
L1 = CMP-0064234-1: Inductor, Unshielded Drum Core, Metal Composite, 3.9 uH, 1.88 A, 0.054 ohm, SMD; Manufacturer: Wurth Elektronik; Isat: 2.57A @ 10% inductance drop; Irms: 1.88A @ 40C rise; Green_Lifecycle: Active; SizeAreaWB_mm2: 27.5; DCR_ohm: 0.054; Green_REACh: Passed; Value: 3.9uH; Imax_A: 1.88A; SizeZ_mm: 3.2; SizeX_mm: 4; SizeY_mm: 4.5; SizeArea_mm2: 18; Ind_H: 3.9µH; AEC Category: Q200
L2 = CMP-0003113-1: Ferrite Bead, 50 ohm @ 100 MHz, 3 A, 1206; Manufacturer: Wurth Elektronik; Ztyp@1GHz_Ohm: 60.942; ZTyp@100MHz_Ohm: 50; SizeAreaWB_mm2: 10.92; DCR_ohm: 0.025; Value1: 0.025 ohm; Value: 50 ohm; Imax_A: 3A; SizeZ_mm: 1.35; SizeX_mm: 3.2; SizeY_mm: 1.6; SizeArea_mm2: 5.12
L3 = CMP-0056527-1: Inductor, Unshielded Drum Core, Ferrite, 2.7 uH, 3.8 A, 0.055 ohm, AEC-Q200 Grade 1, SMD; Manufacturer: Bourns; Isat: 3.8A @ 10% inductance drop; Irms: 4A @ 40C rise; SizeAreaWB_mm2: 56.16; DCR_ohm: 0.055; Value: 2.7uH; Imax_A: 3.8A; SizeZ_mm: 4.5; SizeX_mm: 5.2; SizeY_mm: 5.8; SizeArea_mm2: 30.16; Ind_H: 2.7µH; AEC Qualified: Y; AEC Grade: 1; AEC Category: Q200
L6 = CMP-0062907-1: Inductor, Shielded, Ferrite, 10 uH, 1.13 A, 0.237 ohm, SMD; Manufacturer: TDK; Isat: 1.13A @ 30% inductance drop; Irms: 1.5A @ 40C rise; Green_Lifecycle: Active; SizeAreaWB_mm2: 49; DCR_ohm: 0.237; Green_REACh: Passed; Value: 10uH; Imax_A: 1.13A; SizeZ_mm: 2; SizeX_mm: 5; SizeArea_mm2: 25; Ind_H: 10µH; AEC Category: Q200
L7 L8 = CMP-0064361-1: Inductor, Shielded, Powdered Iron, 4.7 uH, 1.5 A, 0.162 ohm, AEC-Q200 Grade 1, SMD; Manufacturer: Wurth Elektronik; Isat: 2.8A @ 20% inductance drop; Irms: 1.5A @ 40C rise; SizeAreaWB_mm2: 16; DCR_ohm: 0.162; Value: 4.7uH; Imax_A: 1.5A; SizeZ_mm: 1.5; SizeX_mm: 3; SizeArea_mm2: 9; Ind_H: 4.7µH; AEC Qualified: Y; AEC Grade: 1; AEC Category: Q200
Q1 = CMP-0067550-1: MOSFET, N-CH, 30 V, 5 A, AEC-Q101, DQK0006C (WSON-6); Alternate Manufacturer: None; Manufacturer: Texas Instruments; Rdson45_ohm: 0.032; QgTyp_nC: 2.1; SizeAreaWB_mm2: 9.0; Vgs_V: 10V; Value1: 0.032 ohm; VdsMax_V: 30V; U/M: EA; Value: 30V; IdsMax_A: 5A; SizeZ_mm: 0.8; SizeX_mm: 2.0; Value2: 2.1 nC; SizeArea_mm2: 4.0; ChType: N; AEC Qualified: Y; AEC Category: Q101
R1 = CMP-0026518-2: RES, 6.98 k, 1%, 0.063 W, AEC-Q200 Grade 0, 0402; Manufacturer: Vishay-Dale; Power_W: 63mW; TempCo: 100 ppm/C; Value_Code: 6k98; Value: 6.98k; EIA_Code: E96; SizeX_mm: 1; SizeY_mm: 0.5; SizeZ_mm: 0.6; Value2: 0.063W; AEC Qualified: Y; VDC_V: 50V; AEC Category: Q200; AEC Grade: 0
R2 = CMP-0026387-2: RES, 45.3 k, 1%, 0.063 W, AEC-Q200 Grade 0, 0402; Manufacturer: Vishay-Dale; Power_W: 63mW; TempCo: 100 ppm/C; Value_Code: 45k3; Value: 45.3k; EIA_Code: E96; SizeX_mm: 1; SizeY_mm: 0.5; SizeZ_mm: 0.6; Value2: 0.063W; AEC Qualified: Y; VDC_V: 50V; AEC Category: Q200; AEC Grade: 0
R3 = CMP-0020844-3: RES, 10.5 k, 1%, 0.125 W, AEC-Q200 Grade 0, 0805; Manufacturer: Vishay-Dale; Power_W: 125mW; TempCo: 100 ppm/C; Value_Code: 10k5; Value: 10.5k; EIA_Code: E96; SizeX_mm: 2; SizeY_mm: 1.25; SizeZ_mm: 1.45; Value2: 0.125W; SizeArea_mm2: 2.5; AEC Qualified: Y; VDC_V: 150V; AEC Category: Q200; AEC Grade: 0
TP1-TP3 TP5 TP8 TP9 = CMP-0055152-1: as TP4 on sheet TIDA-08007_TPS99000Interface
U1 = CMP-0076397-2: Zero Iq Reverse Polarity Protection Smart Diode Controller, DGK0008A (VSSOP-8); Manufacturer: Texas Instruments; SizeAreaWB_mm2: 23.6; SizeArea_mm2: 14.7; SizeZ_mm: 1.1; Green_REACh: Passed; SizeY_mm: 3; Green_Lifecycle: Active; CompType: IC; SizeX_mm: 4.9; AEC Category: Q200; AEC Qualified: Y
U2 = CMP-0085279-3: Automotive 65-V 1.5-A Synchronous Step-Down Converter, RNX0012B (VQFN-HR-12); Alternate Manufacturer: Texas Instruments; Alternate PartNumber: LMR36015FSC3RNXRQ1; SizeY_mm: 3.0; SizeAreaWB_mm2: 12.0; CompType: IC; SizeX_mm: 2.0; SizeArea_mm2: 6.0; AEC Qualified: Y; SizeZ_mm: 0.9; AEC Category: Q200
U3 = CMP-0074076-5: Automotive Catalog 1.2A Switch, High Voltage Boost Converter in 2x2mm QFN Package, DRV0006A (WSON-6); Manufacturer: Texas Instruments; SizeX_mm: 2; CompType: IC; SizeZ_mm: 0.8; SizeArea_mm2: 4; SizeAreaWB_mm2: 9; U/M: EA
U12 = CMP-0080375-3: Automotive 2.25-MHz Fixed VOUT Dual 800mA Step-Down Converter for ADAS Camera applications, DRC0010J (VSON-10); Manufacturer: Texas Instruments; SizeX_mm: 3; SizeArea_mm2: 9; CompType: IC; AEC Qualified: Y; SizeAreaWB_mm2: 16; SizeZ_mm: 1; AEC Category: Q200

## Sheet TIDA-08007_Hardware.SchDoc: Hardware
size 431 x 279 mm; Date: Not shown in title block; ApprovedBy: Not shown in title block; CheckedBy: Not shown in title block; Author: Not shown in title block; CompanyName: Not shown in title block; DrawnBy: Jake Pulliam; Engineer: Not shown in title block; Organization: Not shown in title block; Address1: Not shown in title block; Address2: Not shown in title block; Address3: Not shown in title block; Address4: Not shown in title block; DocumentNumber: 10; Revision: Use project parameter SCH_Rev; SheetNumber: 10; SheetTotal: 10; PageSetup: Record=PageOptions¦CenterHorizontal=True¦CenterVertical=True¦PrintScale=1.00¦XCorrection=1.00¦YCorrection=1.00¦PrintKind=0¦BorderSize=5000000¦LeftOffset=0¦BottomOffset=0¦Orientation=2¦PaperLength=1000¦PaperWidth=1000¦Scale=100¦PaperSource=15¦PrintQuality=600¦MediaType=1¦DitherType=10¦PaperKind=Letter¦PrintScaleMode=1
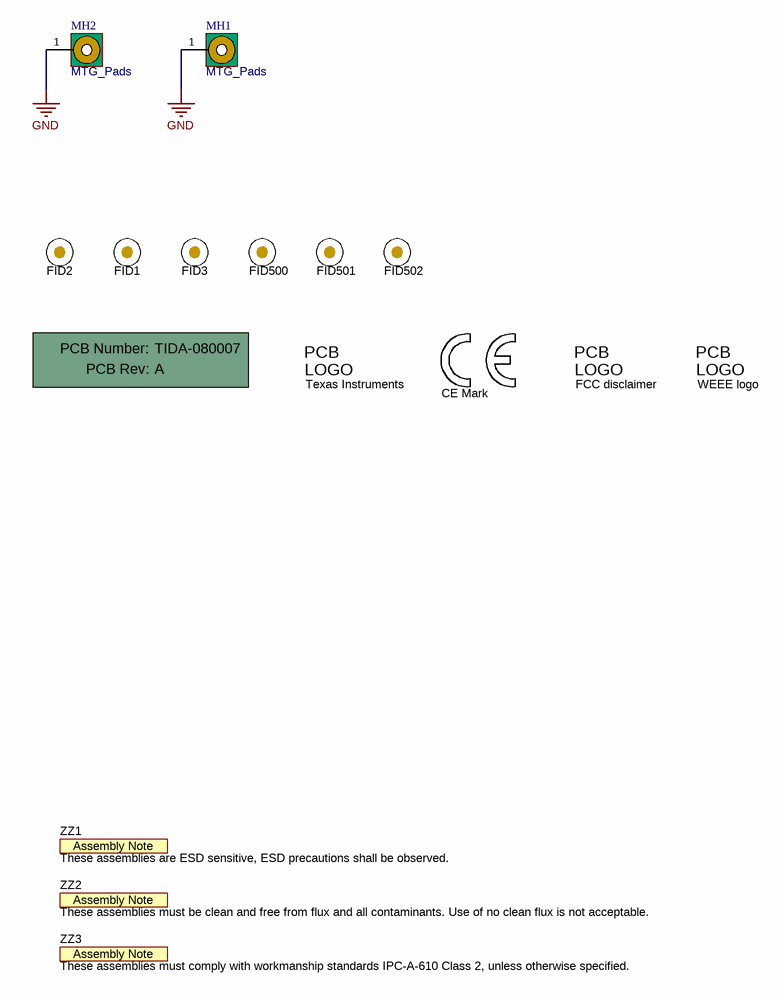
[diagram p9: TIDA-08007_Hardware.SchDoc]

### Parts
!PCB1  Printed Circuit Board  (value not drawn)  (mechanical)
FID1  Fiducial  [Fiducial10-20]  (value not drawn)
FID2  Fiducial  [Fiducial10-20]  (value not drawn)
FID3  Fiducial  [Fiducial10-20]  (value not drawn)
FID500  Fiducial  [Fiducial10-20]  (value not drawn)
FID501  Fiducial  [Fiducial10-20]  (value not drawn)
FID502  Fiducial  [Fiducial10-20]  (value not drawn)
Logo1  CE Mark  [CE_Mark_5mm]  (no BOM)
Logo2  FCC disclaimer  [FCC_disclaimer]  (no BOM)
Logo3  Texas Instruments  [TI_Stacked_Overlay_Small]  (no BOM)
Logo4  WEEE logo  [WEEE_Minimum]  (no BOM)
MH1  MTG_Pads  [MTGP_252mil_157mil_6Via]  (no BOM)
MH2  MTG_Pads  [MTGP_252mil_157mil_6Via]  (no BOM)
ZZ1  These assemblies are ESD sensitive, ESD precautions shall be observed.  [AssemblyNote]  (no BOM)
ZZ2  These assemblies must be clean and free from flux and all contaminants. Use of no clean flux is not acceptable.  [AssemblyNote]  (no BOM)
ZZ3  These assemblies must comply with workmanship standards IPC-A-610 Class 2, unless otherwise specified.  [AssemblyNote]  (no BOM)

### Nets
GND: MH1.1 MH2.1

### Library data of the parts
!PCB1 = CMP-0003618-2: Manufacturer: Any; PartNumber: TIDA-080007
FID1-FID3 FID500-FID502 = CMP-0077181-1: Fiducial mark.  There is nothing to buy or mount.
Logo1 = CMP-0074844-1: SymbolCreator: a0412235
Logo2 = CMP-0074847-1: FCC_disclaimer; Library Reference: Logo
Logo3 = CMP-0074838-1: Texas Instrument Corporate Signature; SymbolCreator: a0412235; Lib Reference: TI_Logo; Library Reference: Logo
Logo4 = CMP-0074769-1
MH1 MH2 = CMP-0078422-2: PCB Mounting Hole; Manufacturer: Any; Key: Mounting Hole (non-standard)
ZZ1 = CMP-0077236-1
ZZ2 = CMP-0077237-1
ZZ3 = CMP-0077238-1

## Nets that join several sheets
1.1V: TIDA-08007_DLPC230Power (37 pins), TIDA-08007_TPS99000Interface (U4.98), TIDA-08007_Power (C55.1 L8.1 TP8.1 U12.4)
1.8V: TIDA-08007_DLPC230Power (C547.1 FB1.1 U7.D10), TIDA-08007_DMDPower (35 pins), TIDA-08007_TPS99000Interface (U4.97), TIDA-08007_Power (C54.1 L7.1 TP9.1 U12.1)
3.3V: TIDA-08007_DLPC230Interface (11 pins), TIDA-08007_DLPC230Power (27 pins), TIDA-08007_DLPC230GPIO (6 pins), TIDA-08007_DMDInterface (C52.1 R25.2 R26.2 U8.1), TIDA-08007_TPS99000Interface (13 pins), TIDA-08007_Power (11 pins)
6.5V: TIDA-08007_TPS99000Interface (12 pins), TIDA-08007_Power (5 pins)
GND: TIDA-08007_DLPC230Interface (27 pins), TIDA-08007_VideoInterface (42 pins), TIDA-08007_DLPC230Power (140 pins), TIDA-08007_DLPC230GPIO (C566.2 R24.1 U6.3), TIDA-08007_DMDInterface (C52.2 R11.1 U8.5), TIDA-08007_DMDPower (66 pins), TIDA-08007_TPS99000Interface (92 pins), TIDA-08007_Power (33 pins), TIDA-08007_Hardware (MH1.1 MH2.1)
V_BIAS: TIDA-08007_DMDPower (C33.1 C570.1 J500.T7 J500.T15), TIDA-08007_TPS99000Interface (C23.1 R4.2 TP6.1 U4.50)
V_OFFSET: TIDA-08007_DMDPower (8 pins), TIDA-08007_TPS99000Interface (5 pins)
V_RESET: TIDA-08007_DMDPower (C32.1 C571.1 J500.T8 J500.T14), TIDA-08007_TPS99000Interface (6 pins)
VIN_PROT: TIDA-08007_TPS99000Interface (R546.2), TIDA-08007_Power (9 pins)
~{HOLD_BOOT}: TIDA-08007_DLPC230Interface (C39.1 J3.4 U501.4), TIDA-08007_DLPC230GPIO (R533.1 U6.1)
ENB_1P1V: TIDA-08007_TPS99000Interface (U4.1), TIDA-08007_Power (U12.7)
ENB_1P8V: TIDA-08007_TPS99000Interface (U4.2), TIDA-08007_Power (U12.9)
ENB_3P3V: TIDA-08007_DLPC230Interface (U500.3), TIDA-08007_TPS99000Interface (U4.3)
PROJ_ON: TIDA-08007_DLPC230Interface (C45.1 J3.6 R17.1 U501.2), TIDA-08007_TPS99000Interface (U4.11)

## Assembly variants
001: not fitted FID1 FID2 FID3 FID500 FID501 FID502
